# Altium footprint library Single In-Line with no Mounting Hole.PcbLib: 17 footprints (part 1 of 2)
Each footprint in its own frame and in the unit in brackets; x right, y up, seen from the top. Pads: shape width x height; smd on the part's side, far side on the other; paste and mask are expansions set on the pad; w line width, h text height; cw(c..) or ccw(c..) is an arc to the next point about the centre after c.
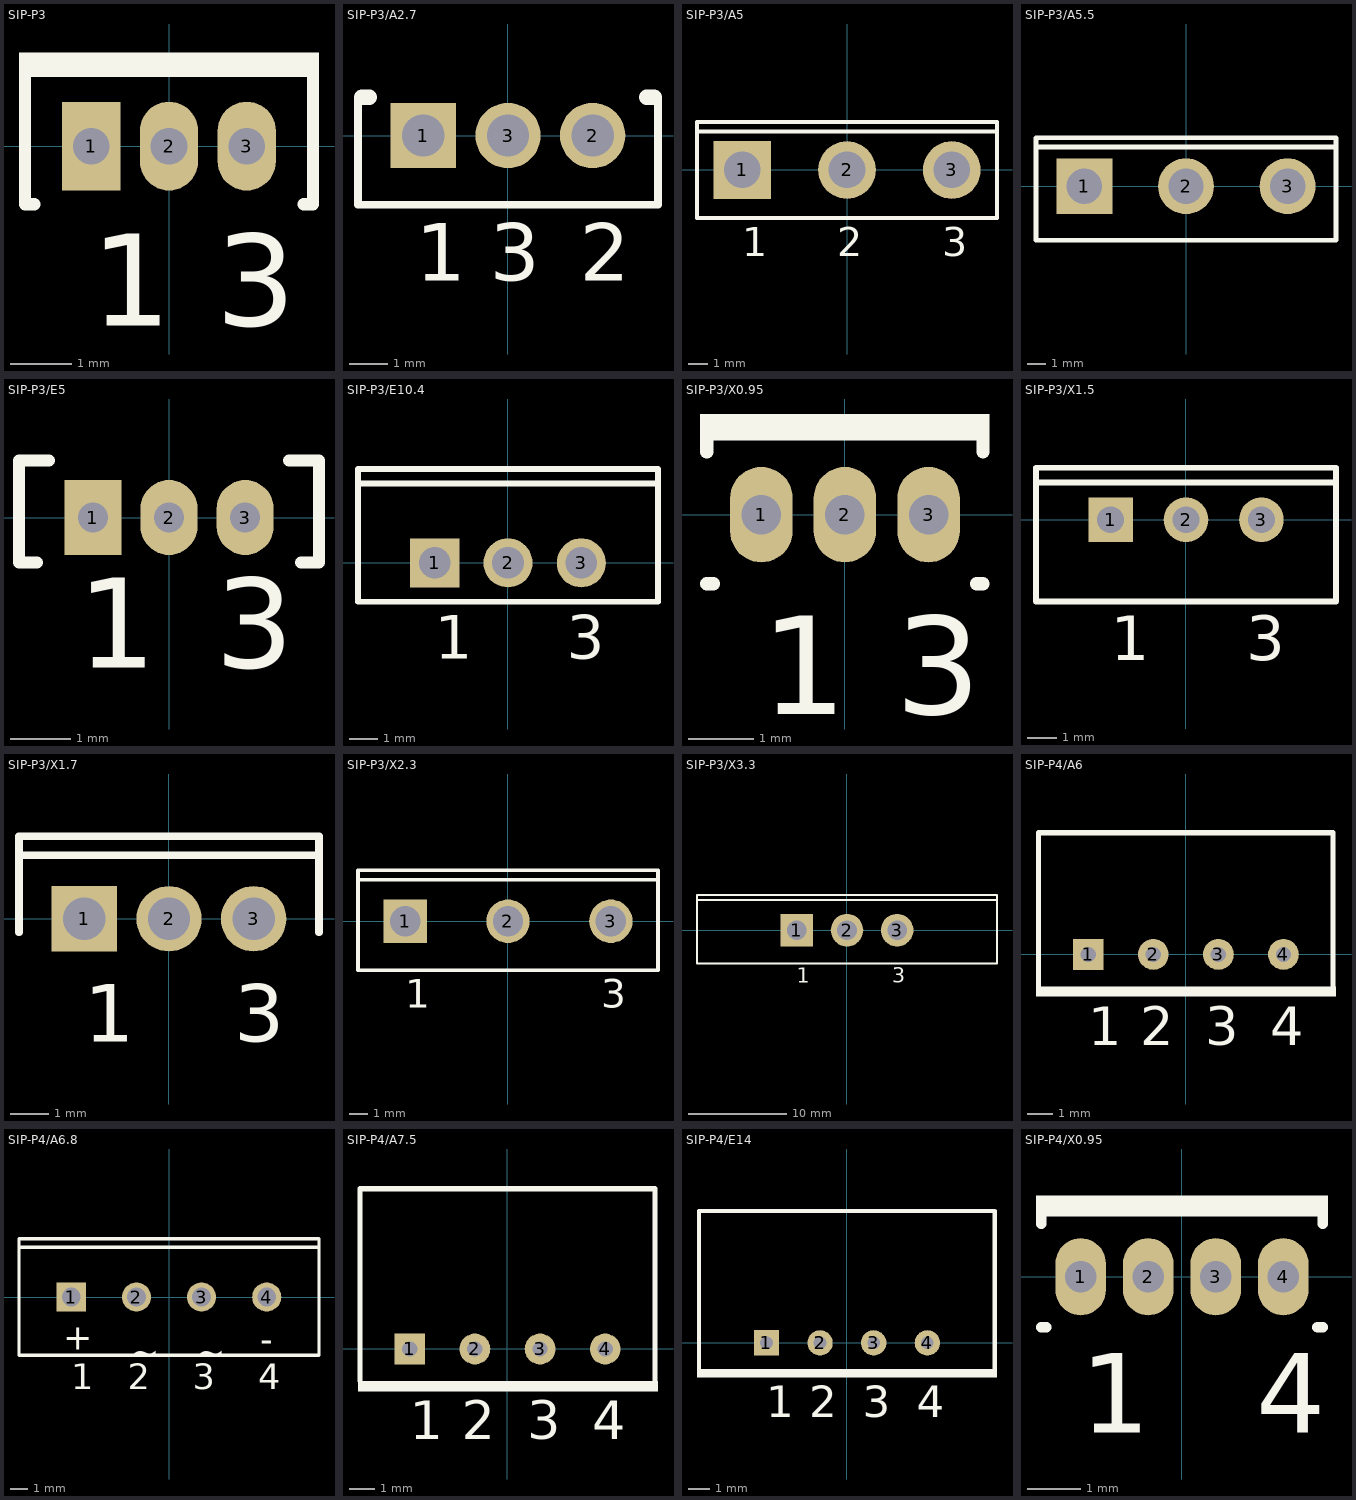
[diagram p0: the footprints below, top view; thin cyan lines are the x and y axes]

## SIP-P3 [mm]
pads (3):
  rect 0.95x1.45 hole 0.6: 1(-1.27,0)
  oval 0.95x1.45 hole 0.6: 2(0,0) 3(1.27,0)
Top Overlay:
  rectangle: -2.45,1.13 2.45,1.53
  lines w0.2: -2.35,1.13 -2.35,-0.95 -2.2,-0.95 ; 2.2,-0.95 2.35,-0.95 2.35,1.13
  text "3" at 0.762,-2.93 h1.5
  text "1" at -1.27,-2.93 h1.5

## SIP-P3/A2.7 [mm]
pads (3):
  rect 1.7x1.7 hole 1.1: 1(-2.2,0)
  round 1.7 hole 1.1: 2(2.2,0) 3(0,0)
Top Overlay:
  lines w0.2: -3.9,1 -3.9,-1.8 3.9,-1.8 3.9,1
  lines w0.4: -3.8,1 -3.6,1 ; 3.6,1 3.8,1
  text "3" at -0.47,-3.78 h1.5
  text "1" at -2.4,-3.78 h1.5
  text "2" at 1.86,-3.78 h1.5

## SIP-P3/A5 [mm]
pads (3):
  rect 3x3 hole 1.9: 1(-5.45,0)
  round 3 hole 1.9: 2(0,0) 3(5.45,0)
Top Overlay:
  lines w0.2: -7.8,2 7.8,2 ; -7.8,-2.5 -7.8,2.5 7.8,2.5 7.8,-2.5 -7.8,-2.5
  text "3" at 4.942,-4.48 h1.5
  text "2" at -0.508,-4.48 h1.5
  text "1" at -5.45,-4.48 h1.5

## SIP-P3/A5.5 [mm]
pads (3):
  rect 3x3 hole 1.9: 1(-5.45,0)
  round 3 hole 1.9: 2(0,0) 3(5.45,0)
Top Overlay:
  lines w0.254: -8.05,2.1 8.05,2.1 ; -8.05,-2.9 -8.05,2.6 8.05,2.6 8.05,-2.9 -8.05,-2.9

## SIP-P3/E5 [mm]
pads (3):
  rect 0.95x1.25 hole 0.5: 1(-1.27,0)
  oval 0.95x1.25 hole 0.5: 2(0,0) 3(1.27,0)
Top Overlay:
  lines w0.2: -2.2,-0.75 -2.5,-0.75 -2.5,0.95 -2,0.95 ; 2,0.95 2.5,0.95 2.5,-0.75 2.2,-0.75
  text "3" at 0.77,-2.5 h1.5
  text "1" at -1.52,-2.5 h1.5

## SIP-P3/E10.4 [mm]
pads (3):
  rect 1.7x1.7 hole 1.1: 1(-2.54,0)
  round 1.7 hole 1.1: 2(0,0) 3(2.54,0)
Top Overlay:
  lines w0.2: -5.2,2.75 5.2,2.75 ; -5.2,-1.35 5.2,-1.35 5.2,3.25 -5.2,3.25 -5.2,-1.35
  text "1" at -2.54,-3.33 h1.5
  text "3" at 2.032,-3.33 h1.5

## SIP-P3/X0.95 [mm]
pads (3):
  oval 0.95x1.45 hole 0.6: 1(-1.27,0) 2(0,0) 3(1.27,0)
Top Overlay:
  rectangle: -2.1,1.13 2.1,1.13
  rectangle: -2.2,1.13 2.2,1.53
  lines w0.2: -2.1,-1.05 -2,-1.05 ; -2.1,0.95 -2.1,1.13 ; 2,-1.05 2.1,-1.05 ; 2.1,0.95 2.1,1.13
  text "3" at 0.762,-3.03 h1.5
  text "1" at -1.27,-3.03 h1.5

## SIP-P3/X1.5 [mm]
pads (3):
  rect 1.5x1.5 hole 0.9: 1(-2.54,0)
  round 1.5 hole 0.9: 2(0,0) 3(2.54,0)
Top Overlay:
  lines w0.2: -5.05,1.25 5.05,1.25 ; -5.05,-2.75 5.05,-2.75 5.05,1.75 -5.05,1.75 -5.05,-2.75
  text "1" at -2.54,-4.73 h1.5
  text "3" at 2.032,-4.73 h1.5

## SIP-P3/X1.7 [mm]
pads (3):
  rect 1.7x1.7 hole 1.1: 1(-2.2,0)
  round 1.7 hole 1.1: 2(0,0) 3(2.2,0)
Top Overlay:
  lines w0.2: -3.9,-0.35 -3.9,2.15 3.9,2.15 3.9,-0.35 ; -3.9,1.65 3.9,1.65
  text "1" at -2.2,-3.2 h1.5
  text "3" at 1.7,-3.2 h1.5

## SIP-P3/X2.3 [mm]
pads (3):
  rect 2.3x2.3 hole 1.6: 1(-5.45,0)
  round 2.3 hole 1.6: 2(0,0) 3(5.45,0)
Top Overlay:
  lines w0.2: -7.95,2.2 7.95,2.2 ; -7.95,-2.6 -7.95,2.7 7.95,2.7 7.95,-2.6 -7.95,-2.6
  text "3" at 4.942,-4.58 h1.5
  text "1" at -5.45,-4.58 h1.5

## SIP-P3/X3.3 [mm]
pads (3):
  rect 3.3x3.3 hole 2: 1(-5.08,0)
  round 3.3 hole 2: 2(0,0) 3(5.08,0)
Top Overlay:
  lines w0.2: -15.2,3.05 15.2,3.05 ; -15.2,-3.35 -15.2,3.55 15.2,3.55 15.2,-3.35 -15.2,-3.35
  text "3" at 4.572,-5.33 h1.5
  text "1" at -5.08,-5.33 h1.5

## SIP-P4/A6 [mm]
pads (4):
  rect 1.2x1.2 hole 0.6: 1(-3.81,0)
  round 1.2 hole 0.6: 2(-1.27,0) 3(1.27,0) 4(3.81,0)
Top Overlay:
  rectangle: -5.85,-1.65 5.86,-1.25
  lines w0.2: -5.75,-1.25 -5.75,4.75 5.75,4.75 5.75,-1.25
  text "1" at -3.81,-3.544 h1.5
  text "2" at -1.778,-3.544 h1.5
  text "3" at 0.762,-3.544 h1.5
  text "4" at 3.302,-3.544 h1.5

## SIP-P4/A6.8 [mm]
pads (4):
  rect 1.7x1.7 hole 1.1: 1(-5.7,0)
  round 1.7 hole 1.1: 2(-1.9,0) 3(1.9,0) 4(5.7,0)
Top Overlay:
  lines w0.2: -8.75,2.9 8.75,2.9 ; -8.75,-3.4 8.75,-3.4 8.75,3.4 -8.75,3.4 -8.75,-3.4
  text "-" at 5.32,-3.19 h1.5
  text "+" at -6.18,-3.08 h1.5
  text "~" at 1.6,-3.94 h1.5
  text "~" at -2.27,-3.94 h1.5
  text "1" at -5.7,-5.38 h1.5
  text "2" at -2.408,-5.38 h1.5
  text "3" at 1.392,-5.38 h1.5
  text "4" at 5.192,-5.38 h1.5

## SIP-P4/A7.5 [mm]
pads (4):
  rect 1.2x1.2 hole 0.6: 1(-3.81,0)
  round 1.2 hole 0.6: 2(-1.27,0) 3(1.27,0) 4(3.81,0)
Top Overlay:
  rectangle: -5.83,-1.65 5.87,-1.25
  lines w0.2: -5.75,-1.25 -5.75,6.25 5.75,6.25 5.75,-1.25
  text "1" at -3.81,-3.52 h1.5
  text "2" at -1.778,-3.52 h1.5
  text "3" at 0.762,-3.52 h1.5
  text "4" at 3.302,-3.52 h1.5

## SIP-P4/E14 [mm]
pads (4):
  rect 1.2x1.2 hole 0.6: 1(-3.81,0)
  round 1.2 hole 0.6: 2(-1.27,0) 3(1.27,0) 4(3.81,0)
Top Overlay:
  rectangle: -7.1,-1.65 7.11,-1.25
  lines w0.2: -7,-1.25 -7,6.25 7,6.25 7,-1.25
  text "1" at -3.81,-3.52 h1.5
  text "2" at -1.778,-3.52 h1.5
  text "3" at 0.762,-3.52 h1.5
  text "4" at 3.302,-3.52 h1.5

## SIP-P4/X0.95 [mm]
pads (4):
  oval 0.95x1.45 hole 0.6: 1(-1.905,0) 2(-0.635,0) 3(0.635,0) 4(1.905,0)
Top Overlay:
  rectangle: -2.746,1.13 2.748,1.53
  lines w0.2: -2.65,-0.95 -2.55,-0.95 ; -2.65,1 -2.65,1.13 ; 2.55,-0.95 2.65,-0.95 ; 2.65,1 2.65,1.13
  text "1" at -1.905,-2.93 h1.5
  text "4" at 1.397,-2.93 h1.5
